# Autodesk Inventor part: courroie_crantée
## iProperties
Shininess: 64.0
Length Units: 11269
Angle Units: 11279
Time Units: 11290
Mass Units: 11283
Length Display Precision: 3
Angle Display Precision: 2
Compacted: True
Part Number: courroie_crantée
Document SubType Name: Modeling
Created: 2004-05
Material: Par défaut
Designer: David
Density: 0.0
Volumn: 0.0
Area: 0.0
PropertySet Name: Model Information
Control State: 0
Master: False
Checked Out: False
Author: David
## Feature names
1. Extrusion1
2. Extrusion2
3. Extrusion3
4. Extrusion4
5. Réseau rectangulaire1 [Rectangular Pattern]
6. Extrusion5
7. Extrusion6
8. Congé1 [Fillet]
9. Symétrie1 [Mirror]
